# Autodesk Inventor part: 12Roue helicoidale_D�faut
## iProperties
Created: 2011-01
Part Number: 12Roue helicoidale_D�faut
Document SubType Name: Modeling
Designer: eric
Density: 1 g/cm^3
Mass: 54.2193 g
Surface Area: 182.103 cm^2
Volume: 54.2193 cm^3
Author: eric
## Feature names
1. Base1
